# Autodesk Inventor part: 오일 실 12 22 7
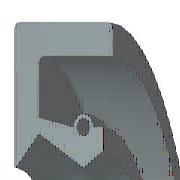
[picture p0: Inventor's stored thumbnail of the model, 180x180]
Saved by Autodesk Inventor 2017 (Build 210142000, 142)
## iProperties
IsCustomPart: 1
Created: 2012-02
Part Number: 오일 실 12 22 7
Material: 고무
Description: 오일-실
Document SubType Name: Modeling
Standard: KS B 2804
Designer: mduedu
Standards Organization: KS
Language: ko-KR
Size Designation: D - 12 22 7
Categories: <MemberInstance><Categories><Category DisplayName="샤프트 부품" InternalName="7f7aeb1f-a693-4053-b835-cee3144e0d98" Mnemonic="SHFT"><Category DisplayName="실링" Intern
Density: 0.93 g/cm^3
Mass: 1.25383 g
Surface Area: 18.4996 cm^2
Volume: 1.3482 cm^3
Appearance: 고무 - 검은색 - 버전 1.1
Author: mduedu
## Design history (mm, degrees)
revolve "본체" stored, may be unused: angle "d17" = 90 deg
revolve "스프링1" stored, may be unused: angle "d18" = 90 deg
body "Solid1"
sketch "스케치1"
  geometry: L1 (0, 11)-(7, 11); L2 (7, 9.25)-(1.75, 9.25); L3 (1.75, 7.75)-(4.9, 6); L4 (4.9, 6)-(0, 6); L5 (0, 0)-(9.586, 0) reference; L6 (4.9, 6)-(6.3, 6.875); L7 (0, 18)-(0, -3) reference; L8 (-1.941, 0)-(11.507, 0) reference; L9 (4.2, 8.1)-(1.75, 8.59); L10 (1.75, 8.59)-(1.75, 9.25); L11 (0, 11)-(0, 6.088); L12 (4.9, 6)-(0, 6); L13 (1.75, 7.75)-(0.152, 6.028); L14 (7, 11)-(7, 9.25); L15 (5.6, 8.1)-(6.3, 8.1); L16 (6.3, 8.1)-(6.3, 6.875); C1 r 0.455 at (4.9, 8.1); A1 r 0.7 centre (4.9, 8.1) between (5.6, 8.1) and (4.2, 8.1); A2 r 0.088 centre (0.088, 6.088) between (0, 6.088) and (0.152, 6.028); 1 further point
  constraints: 28 end point, 5 horizontal alignment, 5 point on line, 4 point on circle, 4 vertical alignment, 3 centre point, 3 tangent, 2 collinear, 2 horizontal, 2 perpendicular, 1 coincident, 1 parallel
  dimensions: "d0" = 22 diameter of L1 L5 (= SD2); "d1" = 1.75 distance of L1.end L2.start (= SD); "d2" = 0.91 diameter of C1 (= SPDI); "d3" = 1.4 diameter of A1 (= SPDA); "d4" = 12 diameter of L3.end L5 (= NND); "d5" = 15.5 diameter of L3.start L5 (= TKDM); "d7" = 17.18 diameter of L9.end L5 (= TKDM + 0.24 x SWDT); "d8" = 1.75 distance between parallel lines of L11 L10 (= SD); "d9" = 4.9 distance from line of L11 C1.centre (= SPDST); "d10" = 16.2 diameter of C1.centre L5 (= HLDM); "d11" = 0.0875 radius of A2 (= 0.25 x LAB); "d12" = 6.3 distance between parallel lines of L11 L16 (= SDI); "d13" = 13.75 diameter of L6.end L5 (= ABDM); "d14" = 7 distance from line of L11 L1.end (= SWDT)
fillet "모깎기1" dims "d6" = 0.3 (= RR)
other parameters: "SD2" = 22 [user parameter; used in 1 equation term], "SWDT" = 7 [user parameter; used in 2 equation terms], "RR" = 0.3 [user parameter; used in 1 equation term], "SD" = 1.75 [user parameter; used in 2 equation terms], "NND" = 12 [user parameter; used in 1 equation term], "SPDA" = 1.4 [user parameter; used in 1 equation term], "SPDI" = 0.91 [user parameter; used in 1 equation term], "TKDM" = 15.5 [user parameter; used in 2 equation terms], "HLDM" = 16.2 [user parameter; used in 1 equation term], "ABDM" = 13.75 [user parameter; used in 1 equation term], "SDI" = 6.3 [user parameter; used in 1 equation term], "SPDST" = 4.9 [user parameter; used in 1 equation term], "LAB" = 0.35 [user parameter; used in 1 equation term], "d15" = 0, "d16" = 0, "d19" = 0
